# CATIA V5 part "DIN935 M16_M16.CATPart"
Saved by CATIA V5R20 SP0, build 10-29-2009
Part number: DIN935 M16_M16
Revision: ANY
Definition: UNKNOWN
Nomenclature: DIN935 M16_M16
Source: Unknown
Bounding box of the stored display mesh (mm): x -12 to 12, y -13.856 to 13.856, z 0 to 19
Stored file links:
  C:\Users\Utente\Desktop\IO LAVORO\3D X SITO CF\X 3D SITO CF 27-09-2020\740T\DIN935 M16_M16.CATPart
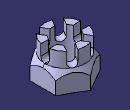
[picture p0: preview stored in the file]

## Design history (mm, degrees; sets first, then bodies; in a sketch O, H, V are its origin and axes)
Body1 "NONE" (main body)
  Solid1: solid without history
